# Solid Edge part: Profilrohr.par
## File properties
Dokumentum tartalom típus: 0
Last saved by: ahadarics
Revision: 76
Sűrűség: 0,000 kg/m^3
Pontosság: 0,990
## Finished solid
Body 1: solid body, 6 faces, 6 edges, 0 vertices.
  Faces by surface: cone 2, cylinder 2, plane 2
  Edges by curve: circle 6
Bounding box of the edges (mm): 26.500 x 26.500 x 69.000, from (-13.25, -13.25, -34.5) to (13.25, 13.25, 34.5).
Cylindrical faces by radius (mm): R12.5 x1, R13.25 x1
Conical faces (half-angle, radius in mm at the cone's reference point): 15 deg R12.567 x2
Planar faces by outward normal: +z 1, -z 1
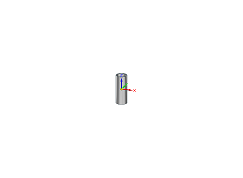
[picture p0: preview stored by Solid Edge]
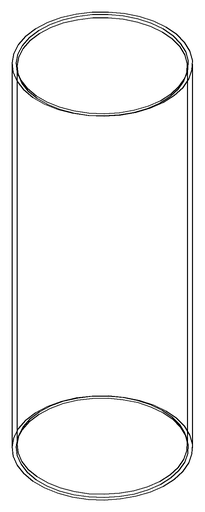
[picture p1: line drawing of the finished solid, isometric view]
